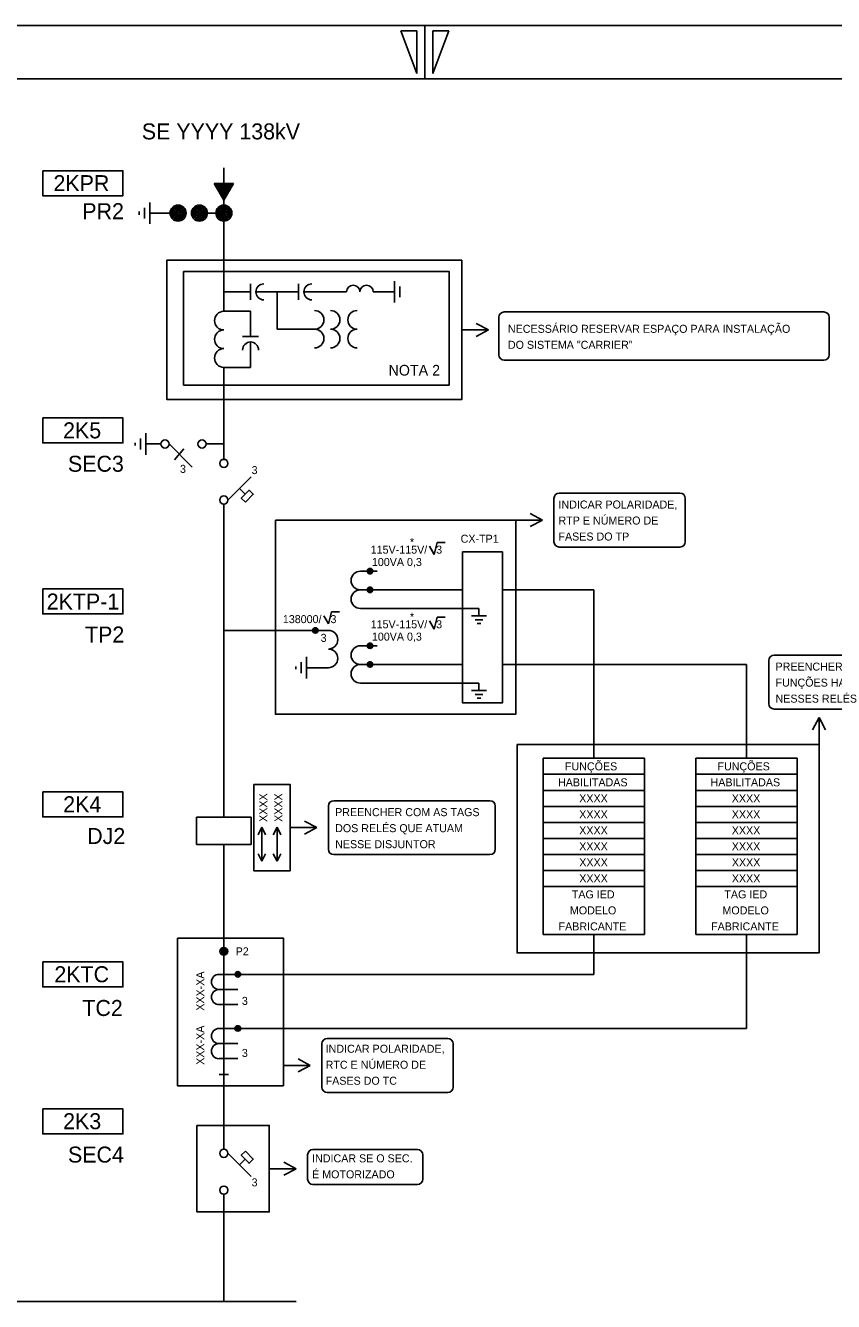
# Model space of a CAD drawing. Extents: x 501 to 1404, y 358 to 952.
# Drawn here: x 958.7 to 1110.2, y 712.8 to 952 of the extents above; entities that cross this region are included whole.
import ezdxf

# ---------------------------------------------------------------- set-up
doc = ezdxf.new("R2010")
doc.units = 0
doc.layers.add('Level 1', color=7, linetype='Continuous')
doc.layers.add('New Level (0)', color=7, linetype='Continuous')

# ---------------------------------------------------------------- blocks, each defined once
blk = doc.blocks.new('_U3')
for p, q in [((-1.47, 0.42), (-0.62, -1.12)), ((-0.62, -1.12), (-0.07, 1.12)), ((-0.07, 1.12), (1.47, 1.12))]:
    blk.add_line(p, q)

msp = doc.modelspace()

# ---------------------------------------------------------------- linework, layer by layer
for p, q in [((995.93, 925.28), (995.93, 898.39)), ((997.74, 922.35), (994.12, 922.35)), ((994.12, 922.35), (995.93, 919.25)), ((997.74, 922.35), (994.12, 922.35)), ((997.56, 922.25), (994.31, 922.25)), ((994.31, 922.25), (995.93, 919.46)), ((997.38, 922.14), (994.49, 922.14)), ((994.49, 922.14), (995.93, 919.67)), ((997.2, 922.04), (994.67, 922.04)), ((994.67, 922.04), (995.93, 919.87)), ((997.02, 921.94), (994.85, 921.94)), ((994.85, 921.94), (995.93, 920.08)), ((996.84, 921.83), (995.03, 921.83)), ((995.03, 921.83), (995.93, 920.29)), ((996.66, 921.73), (995.21, 921.73)), ((995.21, 921.73), (995.93, 920.49)), ((996.48, 921.63), (995.39, 921.63)), ((995.39, 921.63), (995.93, 920.7)), ((996.3, 921.52), (995.57, 921.52)), ((995.57, 921.52), (995.93, 920.9)), ((996.12, 921.42), (995.75, 921.42)), ((995.75, 921.42), (995.93, 921.11)), ((995.93, 919.25), (997.74, 922.35)), ((995.93, 922.35), (995.93, 919.25)), ((995.93, 919.46), (997.56, 922.25)), ((995.93, 919.67), (997.38, 922.14)), ((995.93, 919.87), (997.2, 922.04)), ((995.93, 920.08), (997.02, 921.94)), ((995.93, 920.29), (996.84, 921.83)), ((995.93, 920.49), (996.66, 921.73)), ((995.93, 920.7), (996.48, 921.63)), ((995.93, 920.9), (996.3, 921.52)), ((995.93, 921.11), (996.12, 921.42)), ((982.03, 914.8), (982.03, 918.8)), ((980.03, 917.1), (980.03, 916.5)), ((980.03, 916.8), (980.03, 916.8)), ((981.03, 917.8), (981.03, 915.8)), ((983.35, 916.8), (982.03, 916.8)), ((987.35, 916.8), (983.35, 916.8)), ((995.93, 916.8), (991.35, 916.8)), ((995.93, 887.89), (995.93, 870.68)), ((981.33, 875.58), (981.33, 871.48)), ((979.3, 873.77), (979.3, 873.23)), ((980.31, 872.51), (980.31, 874.55)), ((984.13, 873.53), (981.33, 873.53)), ((990, 869.19), (985.66, 873.53)), ((995.93, 873.53), (992.6, 873.53)), ((986.65, 870.58), (988.45, 872.6)), ((1001.04, 867.35), (996.7, 863.01)), ((999.93, 864.12), (998.87, 865.18)), ((995.93, 803.57), (995.93, 862.24)), ((1021.53, 849.69), (1024.64, 849.69)), ((1021.53, 846.19), (1040.67, 846.19)), ((1048.14, 846.19), (1065.3, 846.19)), ((1021.53, 842.69), (1043.76, 842.69)), ((1043.76, 842.69), (1043.76, 841.29)), ((1045.16, 841.29), (1042.36, 841.29)), ((1043.06, 840.59), (1044.46, 840.59)), ((1043.41, 839.89), (1044.1, 839.89)), ((995.93, 838.59), (1015.53, 838.59)), ((1021.53, 835.7), (1024.64, 835.7)), ((1010.41, 830.56), (1010.41, 832.61)), ((1011.43, 833.64), (1011.43, 829.54)), ((1009.4, 831.83), (1009.4, 831.29)), ((1015.53, 831.59), (1011.43, 831.59)), ((1021.53, 832.2), (1024.64, 832.2)), ((1021.53, 832.2), (1040.67, 832.2)), ((1048.14, 832.2), (1093.9, 832.2)), ((1021.53, 828.7), (1043.76, 828.7)), ((1043.76, 828.7), (1043.76, 827.3)), ((1045.16, 827.3), (1042.36, 827.3)), ((1043.06, 826.6), (1044.46, 826.6)), ((1043.41, 825.9), (1044.1, 825.9)), ((1074.79, 814.61), (1055.81, 814.61)), ((1055.81, 814.61), (1055.81, 781.61)), ((1074.79, 814.61), (1074.79, 781.61)), ((1103.39, 814.61), (1084.41, 814.61)), ((1084.41, 814.61), (1084.41, 781.61)), ((1103.39, 814.61), (1103.39, 781.61)), ((1074.79, 811.61), (1055.81, 811.61)), ((1103.39, 811.61), (1084.41, 811.61)), ((1074.79, 808.61), (1055.81, 808.61)), ((1103.39, 808.61), (1084.41, 808.61)), ((990.81, 798.45), (990.81, 803.57)), ((990.81, 803.57), (1001.05, 803.57)), ((1001.05, 803.57), (1001.05, 798.45)), ((1074.79, 805.61), (1055.81, 805.61)), ((1103.39, 805.61), (1084.41, 805.61)), ((1003.05, 801.69), (1002.34, 800.27)), ((1003.05, 795.32), (1003.05, 801.69)), ((1003.05, 801.69), (1003.76, 800.27)), ((1005.9, 801.69), (1005.19, 800.27)), ((1005.9, 795.32), (1005.9, 801.69)), ((1005.9, 801.69), (1006.61, 800.27)), ((1074.79, 802.61), (1055.81, 802.61)), ((1103.39, 802.61), (1084.41, 802.61)), ((1074.79, 799.61), (1055.81, 799.61)), ((1103.39, 799.61), (1084.41, 799.61)), ((1001.05, 798.45), (990.81, 798.45)), ((995.93, 741.35), (995.93, 798.45)), ((1003.05, 795.32), (1002.34, 796.74)), ((1003.05, 795.32), (1003.76, 796.74)), ((1005.9, 795.32), (1005.19, 796.74)), ((1005.9, 795.32), (1006.61, 796.74)), ((1074.79, 796.61), (1055.81, 796.61)), ((1074.79, 796.61), (1055.81, 796.61)), ((1103.39, 796.61), (1084.41, 796.61)), ((1103.39, 796.61), (1084.41, 796.61)), ((1074.79, 793.61), (1055.81, 793.61)), ((1103.39, 793.61), (1084.41, 793.61)), ((1074.79, 790.61), (1055.81, 790.61)), ((1103.39, 790.61), (1084.41, 790.61)), ((1074.79, 781.61), (1055.81, 781.61)), ((1103.39, 781.61), (1084.41, 781.61)), ((995.02, 774.12), (998.56, 774.12)), ((998.56, 774.11), (1065.3, 774.11)), ((995.02, 771.29), (998.56, 771.29)), ((995.02, 768.46), (998.56, 768.46)), ((995.02, 763.98), (998.56, 763.98)), ((998.56, 763.98), (1093.9, 763.98)), ((995.02, 761.15), (998.56, 761.15)), ((995.02, 758.32), (998.56, 758.32)), ((1001.04, 736.24), (996.7, 740.58)), ((999.93, 739.47), (998.87, 738.41)), ((995.93, 712.81), (995.93, 732.91)), ((1009.5, 712.81), (807.64, 712.81))]:
    msp.add_line(p, q)
for points in [[(999.96, 862.61), (999.2, 863.38), (1000.67, 864.86), (1001.44, 864.09)], [(999.96, 740.98), (999.2, 740.21), (1000.67, 738.73), (1001.44, 739.5)]]:
    msp.add_lwpolyline(points, close=True)
for centre, radius in [((987.35, 916.8), 1.5), ((987.35, 916.8), 1.25), ((987.35, 916.8), 1), ((987.35, 916.8), 0.75), ((987.35, 916.8), 0.5), ((987.35, 916.8), 0.25), ((991.35, 916.8), 1.5), ((991.35, 916.8), 1.25), ((991.35, 916.8), 1), ((991.35, 916.8), 0.75), ((991.35, 916.8), 0.5), ((991.35, 916.8), 0.25), ((995.93, 916.8), 1.5), ((995.93, 916.8), 1.25), ((995.93, 916.8), 1), ((995.93, 916.8), 0.75), ((995.93, 916.8), 0.5), ((995.93, 916.8), 0.25), ((984.9, 873.53), 0.768), ((991.84, 873.53), 0.768), ((995.93, 869.88), 0.768), ((995.93, 863.01), 0.768), ((1023.33, 849.69), 0.511), ((1023.33, 849.69), 0.288), ((1023.33, 846.19), 0.511), ((1023.33, 846.19), 0.288), ((1013.09, 838.58), 0.511), ((1013.09, 838.58), 0.288), ((1023.33, 835.7), 0.511), ((1023.33, 835.7), 0.288), ((1023.33, 832.2), 0.511), ((1023.33, 832.2), 0.288), ((995.92, 778.45), 0.729), ((995.93, 778.45), 0.511), ((995.93, 778.45), 0.288), ((998.56, 774.12), 0.511), ((998.56, 774.12), 0.288), ((998.55, 763.98), 0.511), ((998.55, 763.98), 0.288), ((995.93, 740.58), 0.768), ((995.93, 733.67), 0.768)]:
    msp.add_circle(centre, radius)
for centre, radius, start, end in [((1021.53, 847.94), 1.75, 90, 270), ((1021.53, 844.44), 1.75, 90, 270), ((1015.53, 836.84), 1.75, 270, 90), ((1015.53, 833.34), 1.75, 270, 90), ((1021.53, 833.95), 1.75, 90, 270), ((1021.53, 830.45), 1.75, 90, 270), ((995.02, 772.7), 1.42, 90, 270), ((995.02, 769.87), 1.42, 90, 270), ((995.02, 762.56), 1.42, 90, 270), ((995.02, 759.73), 1.42, 90, 270)]:
    msp.add_arc(centre, radius, start, end)
at = {"layer": 'Level 1'}
for p, q in [((1027.93, 904.04), (1027.93, 900.04)), ((995.93, 902.04), (1000.93, 902.04)), ((1000.93, 903.54), (1000.93, 900.54)), ((1001.93, 902.04), (1009.93, 902.04)), ((1005.93, 902.04), (1005.93, 895.04)), ((1009.93, 903.54), (1009.93, 900.54)), ((1010.93, 902.04), (1018.93, 902.04)), ((1023.93, 902.04), (1027.93, 902.04)), ((1028.93, 901.04), (1028.93, 903.04)), ((1029.93, 902.04), (1029.93, 902.04)), ((1000.93, 898.39), (995.93, 898.39)), ((1000.93, 893.64), (1000.93, 898.39)), ((1005.93, 895.04), (1012.93, 895.04)), ((999.43, 893.64), (1002.43, 893.64)), ((1000.93, 887.89), (1000.93, 892.64)), ((995.93, 887.89), (1000.93, 887.89))]:
    msp.add_line(p, q, dxfattribs=at)
for centre, radius, start, end in [((1003.43, 902.04), 1.5, 90, 270), ((1012.43, 902.04), 1.5, 90, 270), ((1020.18, 902.04), 1.25, 0, 180), ((1022.68, 902.04), 1.25, 0, 180), ((995.93, 896.64), 1.75, 90, 270), ((1012.93, 896.79), 1.75, 270, 90), ((1015.93, 896.79), 1.75, 270, 90), ((1020.93, 896.79), 1.75, 90, 270), ((995.93, 893.14), 1.75, 90, 270), ((1012.93, 893.29), 1.75, 270, 90), ((1015.93, 893.29), 1.75, 270, 90), ((1020.93, 893.29), 1.75, 90, 270), ((1000.93, 891.14), 1.5, 0, 180), ((995.93, 889.64), 1.75, 90, 270)]:
    msp.add_arc(centre, radius, start, end, dxfattribs=at)
at = {"layer": 'New Level (0)'}
for p, q in [((1403.58, 951.96), (562.58, 951.96)), ((1403.58, 951.96), (562.58, 951.96)), ((1033.58, 951.96), (1033.58, 941.96)), ((1032.08, 950.96), (1029.08, 950.96)), ((1029.08, 950.96), (1032.08, 942.96)), ((1032.08, 942.96), (1032.08, 950.96)), ((1035.08, 942.96), (1035.08, 950.96)), ((1035.08, 950.96), (1038.08, 950.96)), ((1038.08, 950.96), (1035.08, 942.96)), ((1393.58, 941.96), (572.58, 941.96)), ((1047.47, 890.24), (1047.47, 897.27)), ((1048.47, 898.27), (1078.55, 898.27)), ((1078.55, 898.27), (1108.42, 898.27)), ((1109.42, 897.27), (1109.42, 890.24)), ((1040.53, 894.9), (1045.56, 894.9)), ((1045.56, 894.9), (1043.26, 896.11)), ((1045.56, 894.9), (1043.26, 893.69)), ((1108.42, 889.24), (1048.47, 889.24)), ((1057.82, 855.21), (1057.82, 863.32)), ((1058.82, 864.32), (1066.18, 864.32)), ((1066.18, 864.32), (1081.44, 864.32)), ((1082.44, 863.32), (1082.44, 855.21)), ((1050.64, 859.27), (1055.67, 859.27)), ((1055.67, 859.27), (1053.37, 860.48)), ((1055.67, 859.27), (1053.37, 858.06)), ((1081.44, 854.21), (1058.82, 854.21)), ((1065.3, 846.19), (1065.3, 814.61)), ((1098.08, 824.84), (1098.08, 832.95)), ((1099.08, 833.95), (1106.43, 833.95)), ((1106.43, 833.95), (1124.09, 833.95)), ((1093.9, 832.2), (1093.9, 814.61)), ((1124.09, 823.84), (1099.08, 823.84)), ((1107.52, 822.24), (1106.31, 819.95)), ((1107.52, 817.22), (1107.52, 822.24)), ((1107.52, 822.24), (1108.73, 819.95)), ((1016.53, 806.67), (1023.88, 806.67)), ((1023.88, 806.67), (1045.82, 806.67)), ((1015.53, 797.56), (1015.53, 805.67)), ((1046.82, 805.67), (1046.82, 797.56)), ((1008.34, 801.62), (1013.37, 801.62)), ((1013.37, 801.62), (1011.07, 802.82)), ((1013.37, 801.62), (1011.07, 800.41)), ((1045.82, 796.56), (1016.53, 796.56)), ((1065.3, 781.61), (1065.3, 774.11)), ((1093.9, 781.61), (1093.9, 763.98)), ((1014.29, 752.99), (1014.29, 761.1)), ((1015.29, 762.1), (1022.64, 762.1)), ((1022.64, 762.1), (1037.91, 762.1)), ((1038.91, 761.1), (1038.91, 752.99)), ((1012.13, 757.05), (1009.84, 758.26)), ((1007.1, 757.05), (1012.13, 757.05)), ((1012.13, 757.05), (1009.84, 755.84)), ((995.04, 755.37), (996.83, 755.37)), ((1037.91, 751.99), (1015.29, 751.99)), ((1011.64, 735.74), (1011.64, 740.29)), ((1012.64, 741.29), (1019.99, 741.29)), ((1019.99, 741.29), (1032.22, 741.29)), ((1033.22, 740.29), (1033.22, 735.74)), ((1004.45, 737.69), (1009.48, 737.69)), ((1009.48, 737.69), (1007.18, 738.9)), ((1009.48, 737.69), (1007.18, 736.48)), ((1032.22, 734.74), (1012.64, 734.74))]:
    msp.add_line(p, q, dxfattribs=at)
for points in [[(961.98, 924.73), (977, 924.73), (977, 920.04), (961.98, 920.04)], [(985.25, 907.95), (1040.53, 907.95), (1040.53, 881.85), (985.25, 881.85)], [(988.39, 905.86), (1038.14, 905.86), (1038.14, 884.57), (988.39, 884.57)], [(961.98, 878.4), (977, 878.4), (977, 873.72), (961.98, 873.72)], [(1005.58, 859.27), (1050.64, 859.27), (1050.64, 822.86), (1005.58, 822.86)], [(1040.67, 853.29), (1048.14, 853.29), (1048.14, 824.99), (1040.67, 824.99)], [(961.98, 846.35), (977, 846.35), (977, 841.67), (961.98, 841.67)], [(1050.91, 817.22), (1107.52, 817.22), (1107.52, 778.15), (1050.91, 778.15)], [(961.98, 808.32), (977, 808.32), (977, 803.64), (961.98, 803.64)], [(1001.56, 809.72), (1008.34, 809.72), (1008.34, 793.51), (1001.56, 793.51)], [(987.21, 780.91), (1007.1, 780.91), (1007.1, 753.23), (987.21, 753.23)], [(961.98, 776.46), (977, 776.46), (977, 771.77), (961.98, 771.77)], [(961.98, 748.9), (977, 748.9), (977, 744.22), (961.98, 744.22)], [(990.89, 745.8), (1004.45, 745.8), (1004.45, 729.58), (990.89, 729.58)]]:
    msp.add_lwpolyline(points, close=True, dxfattribs=at)
for centre, start, end in [((1048.47, 897.27), 90, 180), ((1108.42, 897.27), 0, 90), ((1048.47, 890.24), 180, 270), ((1108.42, 890.24), 270, 0), ((1058.82, 863.32), 90, 180), ((1081.44, 863.32), 0, 90), ((1058.82, 855.21), 180, 270), ((1081.44, 855.21), 270, 0), ((1099.08, 832.95), 90, 180), ((1099.08, 824.84), 180, 270), ((1016.53, 805.67), 90, 180), ((1045.82, 805.67), 0, 90), ((1016.53, 797.56), 180, 270), ((1045.82, 797.56), 270, 0), ((1015.29, 761.1), 90, 180), ((1037.91, 761.1), 0, 90), ((1015.29, 752.99), 180, 270), ((1037.91, 752.99), 270, 0), ((1012.64, 740.29), 90, 180), ((1032.22, 740.29), 0, 90), ((1012.64, 735.74), 180, 270), ((1032.22, 735.74), 270, 0)]:
    msp.add_arc(centre, 1, start, end, dxfattribs=at)

# ---------------------------------------------------------------- block references
for p in [(1035.96, 853.94), (1016.15, 840.92), (1035.96, 839.95)]:
    msp.add_blockref('_U3', p)

# ---------------------------------------------------------------- texts
for s, height, p in [('SE YYYY 138kV', 3, (980.55, 930.61)), ('2KPR', 3, (963.99, 920.91)), ('PR2', 3, (969.39, 915.66)), ('NECESSÁRIO RESERVAR ESPAÇO PARA INSTALAÇÃO ', 1.5, (1049.18, 894.36)), ('DO SISTEMA "CARRIER"', 1.5, (1049.18, 891.36)), ('NOTA 2', 2, (1026.8, 886.35)), ('2K5', 3, (965.79, 874.58)), ('SEC3', 3, (966.7, 868.32)), ('3', 1.5, (987.71, 868.11)), ('3', 1.5, (1001.13, 867.88)), ('INDICAR POLARIDADE, ', 1.5, (1058.66, 861.43)), ('RTP E NÚMERO DE ', 1.5, (1058.66, 858.43)), ('CX-TP1', 1.5, (1040.32, 855.02)), ('FASES DO TP', 1.5, (1058.66, 855.43)), ('115V-115V/   3', 1.5, (1023.46, 852.97)), ('*', 1.5, (1030.82, 854.39)), ('100VA 0,3', 1.5, (1023.68, 850.66)), ('2KTP-1', 3, (962.72, 842.5)), ('*', 1.5, (1030.82, 840.4)), ('138000/   3', 1.5, (1006.99, 839.95)), ('115V-115V/   3', 1.5, (1023.46, 838.98)), ('TP2', 3, (969.9, 836.31)), ('3', 1.5, (1014.07, 836.44)), ('100VA 0,3', 1.5, (1023.68, 836.67)), ('PREENCHER COM AS ', 1.5, (1099.35, 831.05)), ('FUNÇÕES HABILITADAS ', 1.5, (1099.35, 828.05)), ('NESSES RELÉS', 1.5, (1099.35, 825.05)), ('FUNÇÕES ', 1.5, (1059.87, 812.36)), ('FUNÇÕES ', 1.5, (1088.47, 812.36)), ('HABILITADAS', 1.5, (1058.57, 809.36)), ('HABILITADAS', 1.5, (1087.17, 809.36)), ('2K4', 3, (965.81, 804.5)), ('XXXX', 1.5, (1062.55, 806.36)), ('XXXX', 1.5, (1091.15, 806.36)), ('PREENCHER COM AS TAGS ', 1.5, (1016.79, 803.77)), ('XXXX', 1.5, (1062.55, 803.36)), ('XXXX', 1.5, (1091.15, 803.36)), ('DJ2', 3, (970.31, 798.55)), ('DOS RELÉS QUE ATUAM ', 1.5, (1016.79, 800.77)), ('XXXX', 1.5, (1062.55, 800.36)), ('XXXX', 1.5, (1091.15, 800.36)), ('NESSE DISJUNTOR', 1.5, (1016.79, 797.77)), ('XXXX', 1.5, (1062.55, 797.36)), ('XXXX', 1.5, (1091.15, 797.36)), ('XXXX', 1.5, (1062.56, 794.36)), ('XXXX', 1.5, (1091.16, 794.36)), ('XXXX', 1.5, (1062.56, 791.36)), ('XXXX', 1.5, (1091.16, 791.36)), ('TAG IED', 1.5, (1061.16, 788.36)), ('TAG IED', 1.5, (1089.76, 788.36)), ('MODELO', 1.5, (1060.8, 785.36)), ('MODELO', 1.5, (1089.4, 785.36)), ('FABRICANTE', 1.5, (1058.67, 782.36)), ('FABRICANTE', 1.5, (1087.27, 782.36)), ('P2', 1.5, (998.14, 777.68)), ('2KTC', 3, (964.16, 772.64)), ('TC2', 3, (969.4, 766.32)), ('3', 1.5, (999.31, 768.4)), ('INDICAR POLARIDADE, ', 1.5, (1015.01, 759.43)), ('3', 1.5, (999.31, 758.64)), ('RTC E NÚMERO DE ', 1.5, (1015.01, 756.43)), ('FASES DO TC', 1.5, (1015.01, 753.43)), ('2K3', 3, (965.8, 745.1)), ('SEC4', 3, (966.71, 738.84)), ('INDICAR SE O SEC. ', 1.5, (1012.47, 738.89)), ('É MOTORIZADO', 1.5, (1012.47, 735.89)), ('3', 1.5, (1001.13, 734.38))]:
    msp.add_text(s, height=height).set_placement(p)
for s, p in [('XXXX', (1004.05, 802.69)), ('XXXX', (1006.9, 802.69)), ('XXX-XA', (992.24, 767.3)), ('XXX-XA', (992.24, 757.16))]:
    msp.add_text(s, height=1.5, rotation=90).set_placement(p)

doc.saveas('drawing.dxf')
